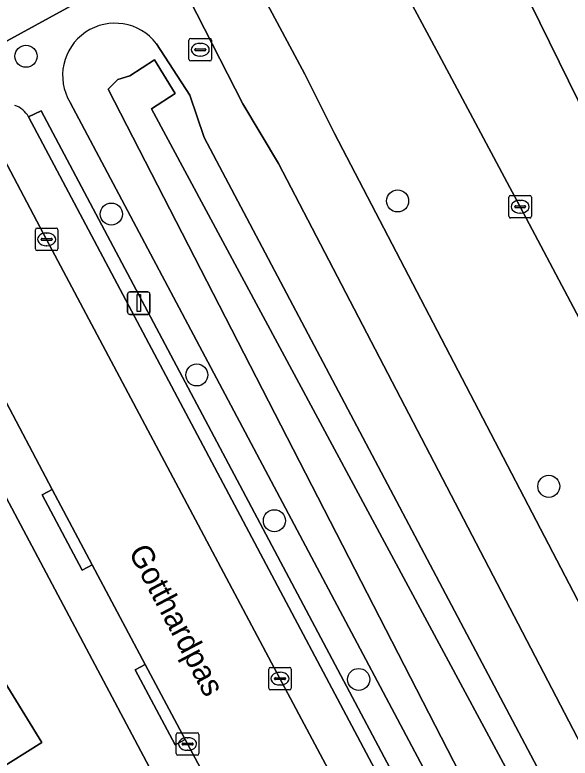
# Model space of a CAD drawing. Extents: x 158835 to 160077, y 386387 to 387778.
# Drawn here: x 159154.69 to 159179.31, y 387215.61 to 387248.58 of the extents above; entities that cross this region are included whole.
import ezdxf

# ---------------------------------------------------------------- set-up
doc = ezdxf.new("R2010")
doc.units = 0
for name, color, linetype in [('IMGEO_Berm_groen', 7, 'Continuous'), ('IMGEO_Boom', 7, 'Continuous'), ('IMGEO_Erf', 7, 'Continuous'), ('IMGEO_Fietspad_gesloten', 7, 'Continuous'), ('IMGEO_Kolk', 7, 'Continuous'), ('IMGEO_Lichtmast', 7, 'Continuous'), ('IMGEO_Muur', 7, 'Continuous'), ('IMGEO_Oever', 7, 'Continuous'), ('IMGEO_Openbare_ruimte_label', 7, 'Continuous'), ('IMGEO_Pand', 7, 'Continuous'), ('IMGEO_Parkeervlak_open', 7, 'Continuous'), ('IMGEO_Rijbaan_lokaal_gesloten', 7, 'Continuous'), ('IMGEO_Rijbaan_lokaal_open', 7, 'Continuous'), ('IMGEO_Rioolput', 7, 'Continuous'), ('IMGEO_Voetpad_open', 7, 'Continuous'), ('IMGEO_Waterloop', 7, 'Continuous')]:
    doc.layers.add(name, color=color, linetype=linetype)

msp = doc.modelspace()

# ---------------------------------------------------------------- linework, layer by layer
at = {"layer": 'IMGEO_Berm_groen'}
for points in [[(159173.432, 387257.503), (159177.113, 387250), (159193.758, 387216.083)], [(159177.093, 387240.071), (159173.489, 387246.828), (159171.786, 387250), (159169.284, 387254.658), (159169.01, 387255.049)], [(159164.099, 387252.402), (159167.543, 387245.956), (159168.854, 387243.324), (159184.918, 387212.468), (159185.422, 387211.502)], [(159183.318, 387205.34), (159181.452, 387208.773), (159183.16, 387209.722), (159166.374, 387241.982), (159164.798, 387244.63), (159161.399, 387251.305), (159159.017, 387250), (159152.136, 387246.23), (159152.49, 387245.539)], [(159160.968, 387247.3), (159162.44, 387245.024), (159163.073, 387243.144), (159178.931, 387213.166)], [(159174.966, 387211.103), (159157.135, 387244.693)], [(159155.293, 387244.056), (159155.849, 387244.332), (159181.029, 387196.88), (159182.268, 387197.547), (159183.697, 387203.232)], [(159190.658, 387214.426), (159186.955, 387221.448), (159177.093, 387240.071)]]:
    msp.add_lwpolyline(points, dxfattribs=at)
for centre, radius, start, end in [((159159.124, 387245.89), 2.321, 37.4044, 211.0384), ((159154.345, 387243.542), 1.079, 28.4774, 71.7269)]:
    msp.add_arc(centre, radius, start, end, dxfattribs=at)
at = {"layer": 'IMGEO_Boom'}
for centre in [(159155.18, 387246.747), (159171.656, 387240.328), (159158.963, 387239.743), (159162.755, 387232.609), (159178.362, 387227.668), (159166.196, 387226.141), (159169.93, 387219.1)]:
    msp.add_circle(centre, 0.489, dxfattribs=at)
at = {"layer": 'IMGEO_Erf'}
for points in [[(159172.316, 387193.221), (159148.576, 387237.925)], [(159153.839, 387219.595), (159155.887, 387216.302), (159153.837, 387215.039), (159155.381, 387212.544), (159156.527, 387210.691), (159158.028, 387211.625), (159160.083, 387208.332), (159158.036, 387207.072), (159159.605, 387204.57), (159160.755, 387202.738), (159162.234, 387203.659), (159164.275, 387200.364), (159162.228, 387199.102), (159163.815, 387196.599), (159164.965, 387194.785), (159166.444, 387195.705), (159168.583, 387192.261)]]:
    msp.add_lwpolyline(points, dxfattribs=at)
at = {"layer": 'IMGEO_Fietspad_gesloten'}
for points in [[(159155.202, 387263.464), (159156.5, 387260.927), (159158.389, 387257.216), (159160.434, 387253.201), (159161.399, 387251.305), (159164.798, 387244.63), (159166.374, 387241.982), (159183.16, 387209.722), (159185.501, 387205.46), (159188.207, 387200.346), (159189.487, 387197.93)], [(159168.854, 387243.324), (159167.543, 387245.956), (159164.099, 387252.402), (159162.674, 387255.076), (159158.593, 387263.089)], [(159189.383, 387197.27), (159192.303, 387199.251), (159192.259, 387199.236), (159192.214, 387199.226), (159192.168, 387199.22), (159192.122, 387199.218), (159192.076, 387199.22), (159192.03, 387199.227), (159191.985, 387199.237), (159191.941, 387199.251), (159191.898, 387199.269), (159191.858, 387199.291), (159191.819, 387199.317), (159191.783, 387199.345), (159191.75, 387199.377), (159191.719, 387199.412), (159191.692, 387199.449), (159191.668, 387199.489), (159190.28, 387202.148), (159190.129, 387202.442), (159186.868, 387208.811), (159185.422, 387211.502), (159184.918, 387212.468), (159168.854, 387243.324)]]:
    msp.add_lwpolyline(points, dxfattribs=at)
at = {"layer": 'IMGEO_Kolk'}
for p, q in [((159176.666, 387240.571), (159177.518, 387240.571)), ((159176.591, 387239.645), (159176.591, 387240.497)), ((159177.079, 387240.351), (159177.104, 387240.351)), ((159177.592, 387240.497), (159177.592, 387239.645)), ((159176.85, 387240.065), (159176.85, 387240.077)), ((159177.288, 387240.028), (159176.89, 387240.028)), ((159176.893, 387240.114), (159177.291, 387240.114)), ((159177.334, 387240.077), (159177.334, 387240.065)), ((159177.518, 387239.571), (159176.666, 387239.571)), ((159177.102, 387239.791), (159177.077, 387239.791)), ((159155.595, 387238.197), (159155.595, 387239.049)), ((159155.67, 387239.123), (159156.522, 387239.123)), ((159156.083, 387238.903), (159156.108, 387238.903)), ((159156.596, 387239.049), (159156.596, 387238.197)), ((159155.854, 387238.617), (159155.854, 387238.629)), ((159156.292, 387238.58), (159155.894, 387238.58)), ((159155.897, 387238.666), (159156.295, 387238.666)), ((159156.338, 387238.629), (159156.338, 387238.617)), ((159156.106, 387238.343), (159156.081, 387238.343)), ((159156.522, 387238.123), (159155.67, 387238.123)), ((159165.942, 387218.711), (159165.942, 387219.563)), ((159166.017, 387219.637), (159166.869, 387219.637)), ((159166.43, 387219.417), (159166.455, 387219.417)), ((159166.943, 387219.563), (159166.943, 387218.711)), ((159166.201, 387219.131), (159166.201, 387219.143)), ((159166.639, 387219.094), (159166.241, 387219.094)), ((159166.244, 387219.18), (159166.642, 387219.18)), ((159166.685, 387219.143), (159166.685, 387219.131)), ((159166.453, 387218.857), (159166.428, 387218.857)), ((159166.869, 387218.637), (159166.017, 387218.637)), ((159161.844, 387215.812), (159161.844, 387216.664)), ((159161.919, 387216.738), (159162.771, 387216.738)), ((159162.332, 387216.518), (159162.357, 387216.518)), ((159162.845, 387216.664), (159162.845, 387215.812)), ((159162.103, 387216.232), (159162.103, 387216.244)), ((159162.541, 387216.195), (159162.143, 387216.195)), ((159162.146, 387216.281), (159162.544, 387216.281)), ((159162.587, 387216.244), (159162.587, 387216.232)), ((159162.355, 387215.958), (159162.33, 387215.958)), ((159162.771, 387215.738), (159161.919, 387215.738))]:
    msp.add_line(p, q, dxfattribs=at)
for points in [[(159176.666, 387240.571), (159177.518, 387240.571)], [(159176.591, 387239.645), (159176.591, 387240.497)], [(159177.592, 387240.497), (159177.592, 387239.645)], [(159177.518, 387239.571), (159176.666, 387239.571)], [(159155.595, 387238.197), (159155.595, 387239.049)], [(159155.67, 387239.123), (159156.522, 387239.123)], [(159156.596, 387239.049), (159156.596, 387238.197)], [(159156.522, 387238.123), (159155.67, 387238.123)], [(159165.942, 387218.711), (159165.942, 387219.563)], [(159166.017, 387219.637), (159166.869, 387219.637)], [(159166.943, 387219.563), (159166.943, 387218.711)], [(159166.869, 387218.637), (159166.017, 387218.637)], [(159161.844, 387215.812), (159161.844, 387216.664)], [(159161.919, 387216.738), (159162.771, 387216.738)], [(159162.845, 387216.664), (159162.845, 387215.812)], [(159162.771, 387215.738), (159161.919, 387215.738)]]:
    msp.add_lwpolyline(points, dxfattribs=at)
for centre, radius, start, end in [((159176.668, 387240.495), 0.0765, 91.552, 178.448), ((159176.668, 387240.495), 0.0765, 91.552, 178.448), ((159177.516, 387240.495), 0.0765, 1.552, 88.448), ((159177.516, 387240.495), 0.0765, 1.552, 88.448), ((159176.89, 387240.074), 0.0403, 85.8775, 175.7526), ((159176.887, 387240.064), 0.0366, 178.938, 274.7102), ((159177.291, 387240.071), 0.043, 264.8664, 352.4533), ((159177.295, 387240.076), 0.0386, 1.7309, 96.639), ((159176.668, 387239.647), 0.0765, 181.552, 268.448), ((159176.668, 387239.647), 0.0765, 181.552, 268.448), ((159177.516, 387239.647), 0.0765, 271.552, 358.448), ((159177.516, 387239.647), 0.0765, 271.552, 358.448), ((159155.672, 387239.047), 0.0765, 91.552, 178.448), ((159155.672, 387239.047), 0.0765, 91.552, 178.448), ((159156.52, 387239.047), 0.0765, 1.552, 88.448), ((159156.52, 387239.047), 0.0765, 1.552, 88.448), ((159155.894, 387238.626), 0.0403, 85.8775, 175.7526), ((159155.891, 387238.616), 0.0366, 178.938, 274.7102), ((159156.295, 387238.623), 0.043, 264.8664, 352.4533), ((159156.299, 387238.628), 0.0386, 1.7309, 96.639), ((159155.672, 387238.199), 0.0765, 181.552, 268.448), ((159155.672, 387238.199), 0.0765, 181.552, 268.448), ((159156.52, 387238.199), 0.0765, 271.552, 358.448), ((159156.52, 387238.199), 0.0765, 271.552, 358.448), ((159166.019, 387219.561), 0.0765, 91.552, 178.448), ((159166.019, 387219.561), 0.0765, 91.552, 178.448), ((159166.867, 387219.561), 0.0765, 1.552, 88.448), ((159166.867, 387219.561), 0.0765, 1.552, 88.448), ((159166.241, 387219.14), 0.0403, 85.8775, 175.7526), ((159166.238, 387219.13), 0.0366, 178.938, 274.7102), ((159166.642, 387219.137), 0.043, 264.8664, 352.4533), ((159166.646, 387219.142), 0.0386, 1.7309, 96.639), ((159166.019, 387218.713), 0.0765, 181.552, 268.448), ((159166.019, 387218.713), 0.0765, 181.552, 268.448), ((159166.867, 387218.713), 0.0765, 271.552, 358.448), ((159166.867, 387218.713), 0.0765, 271.552, 358.448), ((159161.921, 387216.662), 0.0765, 91.552, 178.448), ((159161.921, 387216.662), 0.0765, 91.552, 178.448), ((159162.769, 387216.662), 0.0765, 1.552, 88.448), ((159162.769, 387216.662), 0.0765, 1.552, 88.448), ((159162.143, 387216.241), 0.0403, 85.8775, 175.7526), ((159162.14, 387216.231), 0.0366, 178.938, 274.7102), ((159162.544, 387216.238), 0.043, 264.8664, 352.4533), ((159162.548, 387216.243), 0.0386, 1.7309, 96.639), ((159161.921, 387215.814), 0.0765, 181.552, 268.448), ((159161.921, 387215.814), 0.0765, 181.552, 268.448), ((159162.769, 387215.814), 0.0765, 271.552, 358.448), ((159162.769, 387215.814), 0.0765, 271.552, 358.448)]:
    msp.add_arc(centre, radius, start, end, dxfattribs=at)
for centre, major_axis, ratio, start_param, end_param in [((159177.078, 387240.071), (-0.387, 0.002), 0.722429, 4.712389, 7.853982), ((159177.103, 387240.071), (-0.39, 0.002), 0.717154, 1.570796, 4.712389), ((159156.082, 387238.623), (-0.387, 0.002), 0.722429, 4.712389, 7.853982), ((159156.107, 387238.623), (-0.39, 0.002), 0.717154, 1.570796, 4.712389), ((159166.429, 387219.137), (-0.387, 0.002), 0.722429, 4.712389, 7.853982), ((159166.454, 387219.137), (-0.39, 0.002), 0.717154, 1.570796, 4.712389), ((159162.331, 387216.238), (-0.387, 0.002), 0.722429, 4.712389, 7.853982), ((159162.356, 387216.238), (-0.39, 0.002), 0.717154, 1.570796, 4.712389)]:
    msp.add_ellipse(centre, major_axis=major_axis, ratio=ratio, start_param=start_param, end_param=end_param, dxfattribs=at)
at = {"layer": 'IMGEO_Lichtmast'}
for p, q in [((159159.787, 387236.295), (159160.577, 387236.295)), ((159160.577, 387236.295), (159159.787, 387236.295)), ((159159.687, 387235.395), (159159.687, 387236.195)), ((159159.687, 387236.195), (159159.687, 387235.395)), ((159160.677, 387236.195), (159160.677, 387235.395)), ((159160.677, 387235.395), (159160.677, 387236.195)), ((159160.577, 387235.295), (159159.787, 387235.295)), ((159159.787, 387235.295), (159160.577, 387235.295))]:
    msp.add_line(p, q, dxfattribs=at)
msp.add_lwpolyline([(159160.107, 387236.17), (159160.257, 387236.17), (159160.257, 387235.42), (159160.107, 387235.42), (159160.107, 387236.17)], dxfattribs=at)
for centre, start, end in [((159159.787, 387236.195), 90, 180), ((159159.787, 387236.195), 90, 180), ((159160.577, 387236.195), 0, 90), ((159160.577, 387236.195), 360, 90), ((159159.787, 387235.395), 180, 270), ((159159.787, 387235.395), 180, 270), ((159160.577, 387235.395), 270, 0), ((159160.577, 387235.395), 270, 0)]:
    msp.add_arc(centre, 0.1, start, end, dxfattribs=at)
at = {"layer": 'IMGEO_Muur'}
msp.add_lwpolyline([(159160.742, 387244.407), (159161.8, 387245.094), (159160.883, 387246.587), (159159.788, 387245.882)], dxfattribs=at)
at = {"layer": 'IMGEO_Oever'}
for points in [[(159178.931, 387213.166), (159163.073, 387243.144), (159162.44, 387245.024), (159160.968, 387247.3)], [(159157.135, 387244.693), (159174.966, 387211.103)]]:
    msp.add_lwpolyline(points, dxfattribs=at)
msp.add_lwpolyline([(159160.883, 387246.587), (159161.8, 387245.094), (159160.742, 387244.407), (159177.814, 387212.649), (159177.741, 387212.034), (159177.319, 387211.683), (159176.617, 387211.543), (159176.055, 387211.73), (159158.828, 387245.286), (159159.256, 387245.717), (159159.788, 387245.882)], close=True, dxfattribs=at)
msp.add_arc((159159.124, 387245.89), 2.321, 37.4044, 211.0384, dxfattribs=at)
at = {"layer": 'IMGEO_Pand'}
msp.add_lwpolyline([(159153.839, 387219.595), (159152.359, 387218.674), (159151.209, 387220.499), (159149.629, 387223.006), (159141.438, 387217.946), (159140.894, 387217.61), (159145.636, 387209.985), (159153.837, 387215.039), (159155.887, 387216.302)], close=True, dxfattribs=at)
at = {"layer": 'IMGEO_Parkeervlak_open'}
for points in [[(159152.49, 387245.539), (159154.067, 387242.459), (159156.091, 387238.623), (159166.438, 387219.136), (159176.331, 387200.561), (159179.845, 387194.213)], [(159180.171, 387197.186), (159155.293, 387244.056)]]:
    msp.add_lwpolyline(points, dxfattribs=at)
msp.add_arc((159154.345, 387243.542), 1.079, 28.4774, 71.7269, dxfattribs=at)
at = {"layer": 'IMGEO_Rijbaan_lokaal_gesloten'}
msp.add_lwpolyline([(159177.113, 387250), (159173.432, 387257.503), (159169.01, 387255.049), (159169.284, 387254.658), (159171.786, 387250), (159173.489, 387246.828), (159177.093, 387240.071), (159186.955, 387221.448), (159190.658, 387214.426), (159193.758, 387216.083)], close=True, dxfattribs=at)
at = {"layer": 'IMGEO_Rijbaan_lokaal_open'}
for points in [[(159175.449, 387191.521), (159179.845, 387194.213), (159176.331, 387200.561), (159166.438, 387219.136), (159156.091, 387238.623), (159154.067, 387242.459)], [(159154.005, 387231.93), (159156.34, 387227.524), (159158.114, 387224.189), (159160.46, 387219.758), (159162.234, 387216.43), (159162.342, 387216.239), (159164.731, 387211.766), (159166.469, 387208.44), (159169.064, 387203.57), (159170.832, 387200.256), (159171.74, 387198.545), (159174.819, 387192.714)]]:
    msp.add_lwpolyline(points, dxfattribs=at)
at = {"layer": 'IMGEO_Rioolput'}
for p, q in [((159162.407, 387246.61), (159162.407, 387247.462)), ((159162.482, 387247.536), (159163.334, 387247.536)), ((159163.408, 387247.462), (159163.408, 387246.61)), ((159162.895, 387247.316), (159162.92, 387247.316)), ((159162.666, 387247.03), (159162.666, 387247.042)), ((159163.104, 387246.993), (159162.706, 387246.993)), ((159162.709, 387247.079), (159163.107, 387247.079)), ((159163.15, 387247.042), (159163.15, 387247.03)), ((159163.334, 387246.536), (159162.482, 387246.536)), ((159162.918, 387246.756), (159162.893, 387246.756))]:
    msp.add_line(p, q, dxfattribs=at)
for points in [[(159162.407, 387246.61), (159162.407, 387247.462)], [(159162.482, 387247.536), (159163.334, 387247.536)], [(159163.408, 387247.462), (159163.408, 387246.61)], [(159163.334, 387246.536), (159162.482, 387246.536)]]:
    msp.add_lwpolyline(points, dxfattribs=at)
for centre, radius, start, end in [((159162.484, 387247.46), 0.0765, 91.552, 178.448), ((159162.484, 387247.46), 0.0765, 91.552, 178.448), ((159163.332, 387247.46), 0.0765, 1.552, 88.448), ((159163.332, 387247.46), 0.0765, 1.552, 88.448), ((159162.706, 387247.039), 0.0403, 85.8775, 175.7526), ((159162.703, 387247.029), 0.0366, 178.938, 274.7102), ((159163.107, 387247.036), 0.043, 264.8664, 352.4533), ((159163.111, 387247.041), 0.0386, 1.7309, 96.639), ((159162.484, 387246.612), 0.0765, 181.552, 268.448), ((159162.484, 387246.612), 0.0765, 181.552, 268.448), ((159163.332, 387246.612), 0.0765, 271.552, 358.448), ((159163.332, 387246.612), 0.0765, 271.552, 358.448)]:
    msp.add_arc(centre, radius, start, end, dxfattribs=at)
for centre, major_axis, ratio, start_param, end_param in [((159162.894, 387247.036), (-0.387, 0.002), 0.722429, 4.712389, 7.853982), ((159162.919, 387247.036), (-0.39, 0.002), 0.717154, 1.570796, 4.712389)]:
    msp.add_ellipse(centre, major_axis=major_axis, ratio=ratio, start_param=start_param, end_param=end_param, dxfattribs=at)
at = {"layer": 'IMGEO_Voetpad_open'}
for points in [[(159142.098, 387250), (159144.958, 387244.669), (159145.938, 387242.843), (159148.576, 387237.925), (159172.316, 387193.221)], [(159146.168, 387247.111), (159147.676, 387243.793), (159152.136, 387246.23), (159159.017, 387250)], [(159155.849, 387244.332), (159155.293, 387244.056), (159180.171, 387197.186)], [(159180.253, 387196.418), (159181.029, 387196.88), (159155.849, 387244.332)], [(159166.469, 387208.44), (159166.026, 387208.209), (159164.288, 387211.535), (159164.731, 387211.766), (159162.342, 387216.239), (159162.234, 387216.43), (159161.793, 387216.195), (159160.019, 387219.523), (159160.46, 387219.758), (159158.114, 387224.189), (159157.673, 387223.955), (159155.899, 387227.29), (159156.34, 387227.524), (159154.005, 387231.93)]]:
    msp.add_lwpolyline(points, dxfattribs=at)
for points in [[(159158.114, 387224.189), (159156.34, 387227.524), (159155.899, 387227.29), (159157.673, 387223.955)], [(159160.46, 387219.758), (159160.019, 387219.523), (159161.793, 387216.195), (159162.234, 387216.43)]]:
    msp.add_lwpolyline(points, close=True, dxfattribs=at)
at = {"layer": 'IMGEO_Waterloop'}
msp.add_lwpolyline([(159161.8, 387245.094), (159160.883, 387246.587), (159159.788, 387245.882), (159159.256, 387245.717), (159158.828, 387245.286), (159176.055, 387211.73), (159176.617, 387211.543), (159177.319, 387211.683), (159177.741, 387212.034), (159177.814, 387212.649), (159160.742, 387244.407)], close=True, dxfattribs=at)

# ---------------------------------------------------------------- texts
at = {"layer": 'IMGEO_Openbare_ruimte_label'}
msp.add_text('Gotthardpas', height=1, rotation=297.8466, dxfattribs=at).set_placement((159159.704, 387224.765))

doc.saveas('drawing.dxf')
